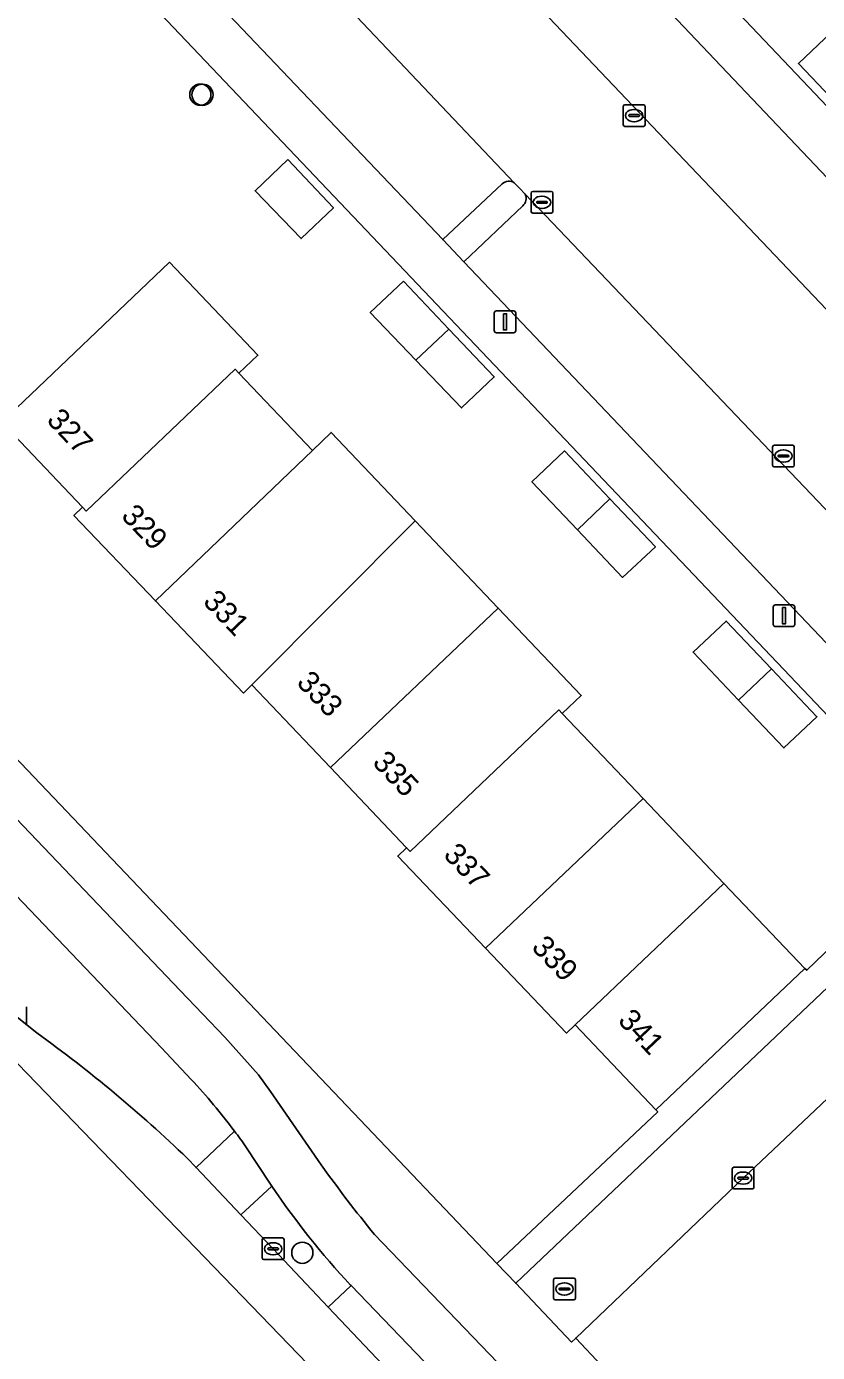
# Model space of a CAD drawing. Extents: x 162523 to 163266, y 381230 to 382050.
# Drawn here: x 163033 to 163069.4, y 381337.1 to 381398.2 of the extents above; entities that cross this region are included whole.
import ezdxf

# ---------------------------------------------------------------- set-up
doc = ezdxf.new("R2010")
doc.units = 0
for name, color, linetype in [('IMGEO_Berm_groen', 7, 'Continuous'), ('IMGEO_Boom', 7, 'Continuous'), ('IMGEO_Drainageput', 7, 'Continuous'), ('IMGEO_Erf', 7, 'Continuous'), ('IMGEO_Fietspad_gesloten', 7, 'Continuous'), ('IMGEO_Groenvoorziening', 7, 'Continuous'), ('IMGEO_Kolk', 7, 'Continuous'), ('IMGEO_Lichtmast', 7, 'Continuous'), ('IMGEO_Pand', 7, 'Continuous'), ('IMGEO_Pand_nummerreeks', 7, 'Continuous'), ('IMGEO_Parkeervlak_open', 7, 'Continuous'), ('IMGEO_Rijbaan_lokaal_gesloten', 7, 'Continuous'), ('IMGEO_Rijbaan_lokaal_open', 7, 'Continuous'), ('IMGEO_Voetpad_open', 7, 'Continuous')]:
    doc.layers.add(name, color=color, linetype=linetype)

msp = doc.modelspace()

# ---------------------------------------------------------------- linework, layer by layer
at = {"layer": 'IMGEO_Berm_groen'}
for points in [[(163040.593, 381349.697), (163039.221, 381351.154), (163032.523, 381358.171)], [(163032.342, 381352.748), (163032.507, 381352.616), (163033.484, 381351.833)], [(163040.401, 381346.065), (163040.814, 381345.631), (163042.585, 381347.314)], [(163044.3, 381344.784), (163042.875, 381343.462), (163044.363, 381341.896), (163046.897, 381339.212), (163047.948, 381340.2), (163047.924, 381340.225)]]:
    msp.add_lwpolyline(points, dxfattribs=at)
for centre, radius, start, end in [((162997.138, 381301.216), 62.315, 46.0316, 54.31979), ((163017.578, 381328.434), 31.334, 37.05214, 42.73378), ((163074.689, 381365.221), 36.622, 213.92097, 223.04219)]:
    msp.add_arc(centre, radius, start, end, dxfattribs=at)
at = {"layer": 'IMGEO_Boom'}
for centre in [(163041.009, 381395.048), (163041.11, 381395.043), (163045.706, 381341.71)]:
    msp.add_circle(centre, 0.489, dxfattribs=at)
at = {"layer": 'IMGEO_Drainageput'}
for p, q in [((163057.275, 381339.618), (163057.275, 381340.47)), ((163057.35, 381340.544), (163058.202, 381340.544)), ((163058.276, 381340.47), (163058.276, 381339.618)), ((163057.534, 381340.038), (163057.534, 381340.05)), ((163057.972, 381340.001), (163057.574, 381340.001)), ((163057.577, 381340.087), (163057.975, 381340.087)), ((163057.786, 381339.764), (163057.761, 381339.764)), ((163057.763, 381340.324), (163057.788, 381340.324)), ((163058.018, 381340.05), (163058.018, 381340.038)), ((163058.202, 381339.544), (163057.35, 381339.544))]:
    msp.add_line(p, q, dxfattribs=at)
for points in [[(163057.275, 381339.618), (163057.275, 381340.47)], [(163057.35, 381340.544), (163058.202, 381340.544)], [(163058.276, 381340.47), (163058.276, 381339.618)], [(163058.202, 381339.544), (163057.35, 381339.544)]]:
    msp.add_lwpolyline(points, dxfattribs=at)
for centre, radius, start, end in [((163057.352, 381340.468), 0.0765, 91.55205, 178.44795), ((163057.352, 381340.468), 0.0765, 91.55205, 178.44795), ((163058.2, 381340.468), 0.0765, 1.55205, 88.44795), ((163058.2, 381340.468), 0.0765, 1.55205, 88.44795), ((163057.574, 381340.047), 0.0403, 85.87752, 175.75265), ((163057.571, 381340.037), 0.0366, 178.93798, 274.71019), ((163057.975, 381340.044), 0.043, 264.86636, 352.45326), ((163057.979, 381340.049), 0.0386, 1.73085, 96.63898), ((163057.352, 381339.62), 0.0765, 181.55205, 268.44795), ((163057.352, 381339.62), 0.0765, 181.55205, 268.44795), ((163058.2, 381339.62), 0.0765, 271.55205, 358.44795), ((163058.2, 381339.62), 0.0765, 271.55205, 358.44795)]:
    msp.add_arc(centre, radius, start, end, dxfattribs=at)
for centre, major_axis, ratio, start_param, end_param in [((163057.762, 381340.044), (-0.387, 0.002), 0.722429, 4.712389, 7.853982), ((163057.787, 381340.044), (-0.39, 0.002), 0.717154, 1.570796, 4.712389)]:
    msp.add_ellipse(centre, major_axis=major_axis, ratio=ratio, start_param=start_param, end_param=end_param, dxfattribs=at)
at = {"layer": 'IMGEO_Erf'}
for points in [[(163072.065, 381403.062), (163068.326, 381406.987), (163064.626, 381410.871), (163060.708, 381414.985), (163062.522, 381416.706), (163058.801, 381420.628), (163058.749, 381420.683), (163051.544, 381413.821), (163078.037, 381385.91), (163085.304, 381392.789), (163085.216, 381392.882), (163081.494, 381396.792), (163079.681, 381395.066), (163075.788, 381399.153)], [(163072.138, 381395.704), (163074.225, 381393.502), (163072.725, 381392.079), (163070.639, 381394.282), (163068.548, 381396.49), (163070.051, 381397.905)], [(163045.031, 381392.064), (163047.14, 381389.843), (163045.649, 381388.418), (163043.527, 381390.626)], [(163050.357, 381386.455), (163052.448, 381384.253), (163054.539, 381382.05), (163053.039, 381380.623), (163050.939, 381382.82), (163048.836, 381385.02)], [(163056.28, 381377.215), (163057.775, 381378.642), (163059.87, 381376.436), (163061.965, 381374.23), (163060.453, 381372.817), (163058.37, 381375.012)], [(163065.793, 381367.165), (163063.696, 381369.379), (163065.214, 381370.807), (163067.307, 381368.603), (163069.4, 381366.399), (163067.878, 381364.963)]]:
    msp.add_lwpolyline(points, close=True, dxfattribs=at)
for points in [[(162981.376, 381418.11), (163033.049, 381363.935), (163054.656, 381341.221), (163062.074, 381348.2), (163061.984, 381348.295), (163058.27, 381352.211), (163057.867, 381351.832), (163054.146, 381355.737), (163050.102, 381359.981), (163050.507, 381360.366), (163047.008, 381364.053), (163043.383, 381367.874), (163042.994, 381367.484), (163038.942, 381371.732), (163035.188, 381375.668), (163035.586, 381376.048), (163031.866, 381379.972), (163039.595, 381387.329), (163043.664, 381383.044), (163042.79, 381382.214), (163046.168, 381378.664), (163047.029, 381379.49), (163050.906, 381375.416), (163054.728, 381371.4), (163058.55, 381367.383), (163057.673, 381366.549), (163061.396, 381362.636), (163065.119, 381358.723), (163068.843, 381354.809), (163068.927, 381354.721), (163075.261, 381360.801), (163037.105, 381400.96)], [(163103.975, 381407.635), (163094.335, 381398.468), (163079.485, 381384.348), (163092.717, 381370.429), (163088.036, 381365.992), (163080.12, 381358.488), (163066, 381345.149), (163058.294, 381337.784), (163059.475, 381336.516), (163059.601, 381336.637), (163072.718, 381322.884), (163084.973, 381309.929), (163089.036, 381305.65), (163100.121, 381293.889)]]:
    msp.add_lwpolyline(points, dxfattribs=at)
at = {"layer": 'IMGEO_Fietspad_gesloten'}
for points in [[(162977.04, 381416.48), (162977.453, 381416.035), (162979.575, 381413.782), (162990.407, 381402.396), (162990.52, 381402.277), (163000.013, 381392.294), (163000.648, 381391.627), (163008.08, 381383.81), (163008.692, 381383.167), (163016.539, 381374.914), (163016.707, 381374.738), (163017.17, 381374.253), (163024.609, 381366.461), (163025.241, 381365.799), (163031.894, 381358.829), (163032.523, 381358.171), (163039.221, 381351.154), (163040.593, 381349.697)], [(163046.572, 381345.757), (163044.245, 381349.131), (163043.683, 381349.9), (163042.131, 381351.633), (163040.075, 381353.795), (163018.683, 381376.223), (162993.271, 381402.913)], [(163043.112, 381346.595), (163044.207, 381344.922), (163044.3, 381344.784)], [(163069.293, 381323.282), (163062.213, 381328.878), (163061.485, 381329.585), (163049.024, 381342.557)], [(163047.924, 381340.225), (163047.948, 381340.2), (163058.375, 381329.349), (163058.969, 381328.729)]]:
    msp.add_lwpolyline(points, dxfattribs=at)
for centre, radius, start, end in [((163017.578, 381328.434), 31.334, 37.05214, 42.73378), ((163015.252, 381326.727), 34.218, 35.49367, 36.98637), ((163102.686, 381386.215), 69.178, 215.79142, 219.13086), ((163074.689, 381365.221), 36.622, 213.92097, 223.04219)]:
    msp.add_arc(centre, radius, start, end, dxfattribs=at)
at = {"layer": 'IMGEO_Groenvoorziening'}
for points in [[(163054.907, 381390.941), (163052.172, 381388.376), (163053.143, 381387.343), (163055.86, 381389.927)], [(163055.973, 381390.461), (163055.712, 381390.735), (163055.466, 381390.994)]]:
    msp.add_lwpolyline(points, dxfattribs=at)
for centre, radius, start, end in [((163055.224, 381390.574), 0.485, 60.05281, 130.77948), ((163055.545, 381390.273), 0.467, 312.32909, 23.77465)]:
    msp.add_arc(centre, radius, start, end, dxfattribs=at)
at = {"layer": 'IMGEO_Kolk'}
for p, q in [((163060.485, 381393.658), (163060.485, 381394.51)), ((163060.56, 381394.584), (163061.412, 381394.584)), ((163060.744, 381394.078), (163060.744, 381394.09)), ((163060.787, 381394.127), (163061.185, 381394.127)), ((163060.973, 381394.364), (163060.998, 381394.364)), ((163061.228, 381394.09), (163061.228, 381394.078)), ((163061.486, 381394.51), (163061.486, 381393.658)), ((163061.412, 381393.584), (163060.56, 381393.584)), ((163061.182, 381394.041), (163060.784, 381394.041)), ((163060.996, 381393.804), (163060.971, 381393.804)), ((163056.24, 381389.666), (163056.24, 381390.518)), ((163056.315, 381390.592), (163057.167, 381390.592)), ((163057.241, 381390.518), (163057.241, 381389.666)), ((163056.499, 381390.086), (163056.499, 381390.098)), ((163056.937, 381390.049), (163056.539, 381390.049)), ((163056.542, 381390.135), (163056.94, 381390.135)), ((163056.728, 381390.372), (163056.753, 381390.372)), ((163056.983, 381390.098), (163056.983, 381390.086)), ((163057.167, 381389.592), (163056.315, 381389.592)), ((163056.751, 381389.812), (163056.726, 381389.812)), ((163067.356, 381377.978), (163067.356, 381378.83)), ((163067.431, 381378.904), (163068.283, 381378.904)), ((163068.357, 381378.83), (163068.357, 381377.978)), ((163067.615, 381378.398), (163067.615, 381378.41)), ((163068.053, 381378.361), (163067.655, 381378.361)), ((163067.658, 381378.447), (163068.056, 381378.447)), ((163067.844, 381378.684), (163067.869, 381378.684)), ((163068.099, 381378.41), (163068.099, 381378.398)), ((163068.283, 381377.904), (163067.431, 381377.904)), ((163067.867, 381378.124), (163067.842, 381378.124)), ((163033.007, 381353.042), (163033.007, 381352.19)), ((163065.499, 381344.723), (163065.499, 381345.575)), ((163065.574, 381345.649), (163066.426, 381345.649)), ((163065.987, 381345.429), (163066.012, 381345.429)), ((163066.5, 381345.575), (163066.5, 381344.723)), ((163066.426, 381344.649), (163065.574, 381344.649)), ((163065.758, 381345.143), (163065.758, 381345.155)), ((163066.196, 381345.106), (163065.798, 381345.106)), ((163065.801, 381345.192), (163066.199, 381345.192)), ((163066.01, 381344.869), (163065.985, 381344.869)), ((163066.242, 381345.155), (163066.242, 381345.143)), ((163043.862, 381341.47), (163043.862, 381342.322)), ((163043.937, 381342.396), (163044.789, 381342.396)), ((163044.863, 381342.322), (163044.863, 381341.47)), ((163044.121, 381341.89), (163044.121, 381341.902)), ((163044.559, 381341.853), (163044.161, 381341.853)), ((163044.164, 381341.939), (163044.562, 381341.939)), ((163044.373, 381341.616), (163044.348, 381341.616)), ((163044.35, 381342.176), (163044.375, 381342.176)), ((163044.605, 381341.902), (163044.605, 381341.89)), ((163044.789, 381341.396), (163043.937, 381341.396))]:
    msp.add_line(p, q, dxfattribs=at)
for points in [[(163060.485, 381393.658), (163060.485, 381394.51)], [(163060.56, 381394.584), (163061.412, 381394.584)], [(163061.486, 381394.51), (163061.486, 381393.658)], [(163061.412, 381393.584), (163060.56, 381393.584)], [(163056.24, 381389.666), (163056.24, 381390.518)], [(163056.315, 381390.592), (163057.167, 381390.592)], [(163057.241, 381390.518), (163057.241, 381389.666)], [(163057.167, 381389.592), (163056.315, 381389.592)], [(163067.356, 381377.978), (163067.356, 381378.83)], [(163067.431, 381378.904), (163068.283, 381378.904)], [(163068.357, 381378.83), (163068.357, 381377.978)], [(163068.283, 381377.904), (163067.431, 381377.904)], [(163033.007, 381353.042), (163033.007, 381352.19)], [(163065.499, 381344.723), (163065.499, 381345.575)], [(163065.574, 381345.649), (163066.426, 381345.649)], [(163066.5, 381345.575), (163066.5, 381344.723)], [(163066.426, 381344.649), (163065.574, 381344.649)], [(163043.862, 381341.47), (163043.862, 381342.322)], [(163043.937, 381342.396), (163044.789, 381342.396)], [(163044.863, 381342.322), (163044.863, 381341.47)], [(163044.789, 381341.396), (163043.937, 381341.396)]]:
    msp.add_lwpolyline(points, dxfattribs=at)
for centre, radius, start, end in [((163060.562, 381394.508), 0.0765, 91.55205, 178.44795), ((163060.562, 381394.508), 0.0765, 91.55205, 178.44795), ((163060.784, 381394.087), 0.0403, 85.87752, 175.75265), ((163061.189, 381394.089), 0.0386, 1.73085, 96.63898), ((163061.41, 381394.508), 0.0765, 1.55205, 88.44795), ((163061.41, 381394.508), 0.0765, 1.55205, 88.44795), ((163060.562, 381393.66), 0.0765, 181.55205, 268.44795), ((163060.562, 381393.66), 0.0765, 181.55205, 268.44795), ((163060.781, 381394.077), 0.0366, 178.93798, 274.71019), ((163061.185, 381394.084), 0.043, 264.86636, 352.45326), ((163061.41, 381393.66), 0.0765, 271.55205, 358.44795), ((163061.41, 381393.66), 0.0765, 271.55205, 358.44795), ((163056.317, 381390.516), 0.0765, 91.55205, 178.44795), ((163056.317, 381390.516), 0.0765, 91.55205, 178.44795), ((163057.165, 381390.516), 0.0765, 1.55205, 88.44795), ((163057.165, 381390.516), 0.0765, 1.55205, 88.44795), ((163056.539, 381390.095), 0.0403, 85.87752, 175.75265), ((163056.536, 381390.085), 0.0366, 178.93798, 274.71019), ((163056.94, 381390.092), 0.043, 264.86636, 352.45326), ((163056.944, 381390.097), 0.0386, 1.73085, 96.63898), ((163056.317, 381389.668), 0.0765, 181.55205, 268.44795), ((163056.317, 381389.668), 0.0765, 181.55205, 268.44795), ((163057.165, 381389.668), 0.0765, 271.55205, 358.44795), ((163057.165, 381389.668), 0.0765, 271.55205, 358.44795), ((163067.433, 381378.828), 0.0765, 91.55205, 178.44795), ((163067.433, 381378.828), 0.0765, 91.55205, 178.44795), ((163068.281, 381378.828), 0.0765, 1.55205, 88.44795), ((163068.281, 381378.828), 0.0765, 1.55205, 88.44795), ((163067.655, 381378.407), 0.0403, 85.87752, 175.75265), ((163067.652, 381378.397), 0.0366, 178.93798, 274.71019), ((163068.056, 381378.404), 0.043, 264.86636, 352.45326), ((163068.06, 381378.409), 0.0386, 1.73085, 96.63898), ((163067.433, 381377.98), 0.0765, 181.55205, 268.44795), ((163067.433, 381377.98), 0.0765, 181.55205, 268.44795), ((163068.281, 381377.98), 0.0765, 271.55205, 358.44795), ((163068.281, 381377.98), 0.0765, 271.55205, 358.44795), ((163065.576, 381345.573), 0.0765, 91.55205, 178.44795), ((163065.576, 381345.573), 0.0765, 91.55205, 178.44795), ((163066.424, 381345.573), 0.0765, 1.55205, 88.44795), ((163066.424, 381345.573), 0.0765, 1.55205, 88.44795), ((163065.576, 381344.725), 0.0765, 181.55205, 268.44795), ((163065.576, 381344.725), 0.0765, 181.55205, 268.44795), ((163065.798, 381345.152), 0.0403, 85.87752, 175.75265), ((163065.795, 381345.142), 0.0366, 178.93798, 274.71019), ((163066.199, 381345.149), 0.043, 264.86636, 352.45326), ((163066.203, 381345.154), 0.0386, 1.73085, 96.63898), ((163066.424, 381344.725), 0.0765, 271.55205, 358.44795), ((163066.424, 381344.725), 0.0765, 271.55205, 358.44795), ((163043.939, 381342.32), 0.0765, 91.55205, 178.44795), ((163043.939, 381342.32), 0.0765, 91.55205, 178.44795), ((163044.787, 381342.32), 0.0765, 1.55205, 88.44795), ((163044.787, 381342.32), 0.0765, 1.55205, 88.44795), ((163044.161, 381341.899), 0.0403, 85.87752, 175.75265), ((163044.158, 381341.889), 0.0366, 178.93798, 274.71019), ((163044.562, 381341.896), 0.043, 264.86636, 352.45326), ((163044.566, 381341.901), 0.0386, 1.73085, 96.63898), ((163043.939, 381341.472), 0.0765, 181.55205, 268.44795), ((163043.939, 381341.472), 0.0765, 181.55205, 268.44795), ((163044.787, 381341.472), 0.0765, 271.55205, 358.44795), ((163044.787, 381341.472), 0.0765, 271.55205, 358.44795)]:
    msp.add_arc(centre, radius, start, end, dxfattribs=at)
for centre, major_axis, ratio, start_param, end_param in [((163060.972, 381394.084), (-0.387, 0.002), 0.722429, 4.712389, 7.853982), ((163060.997, 381394.084), (-0.39, 0.002), 0.717154, 1.570796, 4.712389), ((163056.727, 381390.092), (-0.387, 0.002), 0.722429, 4.712389, 7.853982), ((163056.752, 381390.092), (-0.39, 0.002), 0.717154, 1.570796, 4.712389), ((163067.843, 381378.404), (-0.387, 0.002), 0.722429, 4.712389, 7.853982), ((163067.868, 381378.404), (-0.39, 0.002), 0.717154, 1.570796, 4.712389), ((163065.986, 381345.149), (-0.387, 0.002), 0.722429, 4.712389, 7.853982), ((163066.011, 381345.149), (-0.39, 0.002), 0.717154, 1.570796, 4.712389), ((163044.349, 381341.896), (-0.387, 0.002), 0.722429, 4.712389, 7.853982), ((163044.374, 381341.896), (-0.39, 0.002), 0.717154, 1.570796, 4.712389)]:
    msp.add_ellipse(centre, major_axis=major_axis, ratio=ratio, start_param=start_param, end_param=end_param, dxfattribs=at)
at = {"layer": 'IMGEO_Lichtmast'}
for p, q in [((163054.542, 381384.185), (163054.542, 381384.985)), ((163054.542, 381384.985), (163054.542, 381384.185)), ((163054.642, 381385.085), (163055.432, 381385.085)), ((163055.432, 381385.085), (163054.642, 381385.085)), ((163055.532, 381384.985), (163055.532, 381384.185)), ((163055.532, 381384.185), (163055.532, 381384.985)), ((163055.432, 381384.085), (163054.642, 381384.085)), ((163054.642, 381384.085), (163055.432, 381384.085)), ((163067.487, 381371.552), (163068.277, 381371.552)), ((163068.277, 381371.552), (163067.487, 381371.552)), ((163067.387, 381370.652), (163067.387, 381371.452)), ((163067.387, 381371.452), (163067.387, 381370.652)), ((163068.377, 381371.452), (163068.377, 381370.652)), ((163068.377, 381370.652), (163068.377, 381371.452)), ((163068.277, 381370.552), (163067.487, 381370.552)), ((163067.487, 381370.552), (163068.277, 381370.552))]:
    msp.add_line(p, q, dxfattribs=at)
for points in [[(163054.962, 381384.96), (163055.112, 381384.96), (163055.112, 381384.21), (163054.962, 381384.21), (163054.962, 381384.96)], [(163067.807, 381371.427), (163067.957, 381371.427), (163067.957, 381370.677), (163067.807, 381370.677), (163067.807, 381371.427)]]:
    msp.add_lwpolyline(points, dxfattribs=at)
for centre, start, end in [((163054.642, 381384.985), 90, 180), ((163054.642, 381384.985), 90, 180), ((163055.432, 381384.985), 0, 90), ((163055.432, 381384.985), 360, 90), ((163054.642, 381384.185), 180, 270), ((163054.642, 381384.185), 180, 270), ((163055.432, 381384.185), 270, 0), ((163055.432, 381384.185), 270, 0), ((163067.487, 381371.452), 90, 180), ((163067.487, 381371.452), 90, 180), ((163068.277, 381371.452), 0, 90), ((163068.277, 381371.452), 360, 90), ((163067.487, 381370.652), 180, 270), ((163067.487, 381370.652), 180, 270), ((163068.277, 381370.652), 270, 0), ((163068.277, 381370.652), 270, 0)]:
    msp.add_arc(centre, 0.1, start, end, dxfattribs=at)
at = {"layer": 'IMGEO_Pand'}
for points in [[(163070.051, 381397.905), (163068.548, 381396.49), (163070.639, 381394.282), (163072.138, 381395.704)], [(163045.031, 381392.064), (163043.527, 381390.626), (163045.649, 381388.418), (163047.14, 381389.843)], [(163042.612, 381382.401), (163042.79, 381382.214), (163043.664, 381383.044), (163039.595, 381387.329), (163031.866, 381379.972), (163035.586, 381376.048), (163035.752, 381375.873)], [(163050.357, 381386.455), (163048.836, 381385.02), (163050.939, 381382.82), (163052.448, 381384.253)], [(163052.448, 381384.253), (163050.939, 381382.82), (163053.039, 381380.623), (163054.539, 381382.05)], [(163046.168, 381378.664), (163042.79, 381382.214), (163042.612, 381382.401), (163035.752, 381375.873), (163035.586, 381376.048), (163035.188, 381375.668), (163038.942, 381371.732)], [(163050.906, 381375.416), (163047.029, 381379.49), (163046.168, 381378.664), (163038.942, 381371.732), (163042.994, 381367.484), (163043.383, 381367.874)], [(163057.775, 381378.642), (163056.28, 381377.215), (163058.37, 381375.012), (163059.87, 381376.436)], [(163059.87, 381376.436), (163058.37, 381375.012), (163060.453, 381372.817), (163061.965, 381374.23)], [(163054.728, 381371.4), (163050.906, 381375.416), (163043.383, 381367.874), (163047.008, 381364.053)], [(163057.516, 381366.714), (163057.673, 381366.549), (163058.55, 381367.383), (163054.728, 381371.4), (163047.008, 381364.053), (163050.507, 381360.366), (163050.667, 381360.198)], [(163065.214, 381370.807), (163063.696, 381369.379), (163065.793, 381367.165), (163067.307, 381368.603)], [(163067.307, 381368.603), (163065.793, 381367.165), (163067.878, 381364.963), (163069.4, 381366.399)], [(163061.396, 381362.636), (163057.673, 381366.549), (163057.516, 381366.714), (163050.667, 381360.198), (163050.507, 381360.366), (163050.102, 381359.981), (163054.146, 381355.737)], [(163065.119, 381358.723), (163061.396, 381362.636), (163054.146, 381355.737), (163057.867, 381351.832), (163058.27, 381352.211)], [(163068.843, 381354.809), (163065.119, 381358.723), (163058.27, 381352.211), (163061.984, 381348.295)]]:
    msp.add_lwpolyline(points, close=True, dxfattribs=at)
at = {"layer": 'IMGEO_Parkeervlak_open'}
for points in [[(163073.503, 381381.951), (163076.209, 381384.545), (163050.886, 381411.231)], [(163047.55, 381408.608), (163073.395, 381381.402)], [(163055.466, 381390.994), (163042.921, 381404.231)], [(163042.869, 381403.598), (163040.159, 381401.017), (163052.172, 381388.376), (163054.907, 381390.941)], [(163078.227, 381367.118), (163055.973, 381390.461)], [(163055.86, 381389.927), (163053.143, 381387.343), (163074.889, 381364.471), (163077.618, 381367.083)]]:
    msp.add_lwpolyline(points, dxfattribs=at)
for centre, radius, start, end in [((163055.224, 381390.574), 0.485, 60.05281, 130.77948), ((163055.545, 381390.273), 0.467, 312.32909, 23.77465)]:
    msp.add_arc(centre, radius, start, end, dxfattribs=at)
at = {"layer": 'IMGEO_Rijbaan_lokaal_gesloten'}
for points in [[(162887.11, 381503.092), (162963.914, 381421.653), (162967.157, 381418.214), (163074.793, 381306.702), (163143.693, 381232.736), (163143.732, 381232.914), (163146.87, 381246.552), (163146.483, 381246.256), (163145.74, 381245.612)], [(163033.484, 381351.833), (163032.507, 381352.616), (163032.342, 381352.748)], [(163135.599, 381245.842), (163133.355, 381248.15), (163132.2, 381249.361), (163129.773, 381251.897), (163089.051, 381294.815), (163084.32, 381299.797), (163079.482, 381304.902), (163076.942, 381307.585), (163065.257, 381319.865), (163062.115, 381323.168), (163060.051, 381325.338), (163057.246, 381328.286), (163046.897, 381339.212), (163044.363, 381341.896), (163042.875, 381343.462), (163040.814, 381345.631), (163040.401, 381346.065)]]:
    msp.add_lwpolyline(points, dxfattribs=at)
msp.add_arc((162997.138, 381301.216), 62.315, 46.0316, 54.31979, dxfattribs=at)
at = {"layer": 'IMGEO_Rijbaan_lokaal_open'}
for points in [[(163088.036, 381365.992), (163086.776, 381367.317), (163086.348, 381367.767), (163073.761, 381381.017), (163073.395, 381381.402), (163047.55, 381408.608), (163046.937, 381409.253), (163042.309, 381404.877), (163042.921, 381404.231), (163055.466, 381390.994), (163055.712, 381390.735), (163055.973, 381390.461), (163078.227, 381367.118), (163078.474, 381366.857)], [(163078.452, 381364.011), (163076.711, 381362.355), (163077.679, 381361.329), (163055.529, 381340.304), (163058.101, 381337.6), (163058.294, 381337.784), (163066, 381345.149), (163080.12, 381358.488), (163088.036, 381365.992)]]:
    msp.add_lwpolyline(points, dxfattribs=at)
msp.add_lwpolyline([(163047.948, 381340.2), (163046.897, 381339.212), (163057.246, 381328.286), (163058.375, 381329.349)], close=True, dxfattribs=at)
at = {"layer": 'IMGEO_Voetpad_open'}
for points in [[(163059.601, 381336.637), (163059.475, 381336.516), (163058.294, 381337.784), (163058.101, 381337.6), (163055.529, 381340.304), (163054.656, 381341.221), (163033.049, 381363.935), (162981.376, 381418.11), (162980.035, 381416.858), (162981.388, 381415.366), (162993.271, 381402.913), (163018.683, 381376.223), (163040.075, 381353.795), (163042.131, 381351.633), (163043.683, 381349.9), (163044.245, 381349.131), (163046.572, 381345.757)], [(163092.792, 381400.095), (163085.216, 381392.882), (163085.304, 381392.789), (163078.037, 381385.91), (163051.544, 381413.821)], [(163050.886, 381411.231), (163076.209, 381384.545), (163077.037, 381383.681), (163089.13, 381370.926), (163089.342, 381370.92), (163089.938, 381370.295), (163086.776, 381367.317), (163088.036, 381365.992), (163092.717, 381370.429), (163079.485, 381384.348), (163094.335, 381398.468)], [(163037.105, 381400.96), (163075.261, 381360.801), (163068.927, 381354.721), (163068.843, 381354.809), (163061.984, 381348.295), (163062.074, 381348.2), (163054.656, 381341.221), (163055.529, 381340.304), (163077.679, 381361.329), (163076.711, 381362.355), (163074.894, 381364.25), (163074.889, 381364.471), (163053.143, 381387.343), (163052.172, 381388.376), (163040.159, 381401.017)], [(163042.585, 381347.314), (163040.814, 381345.631), (163042.875, 381343.462), (163044.3, 381344.784), (163044.207, 381344.922)], [(163044.207, 381344.922), (163043.112, 381346.595)], [(163049.024, 381342.557), (163061.485, 381329.585), (163062.213, 381328.878), (163069.293, 381323.282)]]:
    msp.add_lwpolyline(points, dxfattribs=at)
for centre, radius, start, end in [((163015.252, 381326.727), 34.218, 35.49367, 36.98637), ((163102.686, 381386.215), 69.178, 215.79142, 219.13086)]:
    msp.add_arc(centre, radius, start, end, dxfattribs=at)

# ---------------------------------------------------------------- texts
at = {"layer": 'IMGEO_Pand_nummerreeks'}
for s, rotation, p in [('327', 313.4701, (163033.887, 381380.021)), ('329', 313.64771, (163037.322, 381375.605)), ('331', 313.64771, (163041.087, 381371.657)), ('333', 313.49875, (163045.397, 381367.931)), ('335', 313.49875, (163048.89, 381364.25)), ('337', 313.61907, (163052.158, 381359.997)), ('339', 313.61907, (163056.214, 381355.741)), ('341', 313.48156, (163060.192, 381352.364))]:
    msp.add_text(s, height=1, rotation=rotation, dxfattribs=at).set_placement(p)

doc.saveas('drawing.dxf')
